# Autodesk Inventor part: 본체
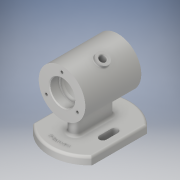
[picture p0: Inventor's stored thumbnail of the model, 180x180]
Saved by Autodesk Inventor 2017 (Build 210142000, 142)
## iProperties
Part Number: 본체
Material: 알루미늄 6061
Document SubType Name: Modeling
Designer: 601-13
Density: 2.7 g/cm^3
Appearance: 알루미늄 - 평지
Mass: 603.033 g
Surface Area: 453.222 cm^2
Volume: 223.346 cm^3
Author: 601-13
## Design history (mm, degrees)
sketch "스케치1"
  geometry: L1 (35.496, -38)-(-35.496, -38); L2 (35.496, 38)-(-35.496, 38); A1 r 52 centre (0, 0) between (-35.496, 38) and (-35.496, -38); A2 r 52 centre (0, 0) between (35.496, -38) and (35.496, 38); 3 further points
  constraints: 4 end point, 4 point on circle, 2 centre point, 2 horizontal, 2 midpoint, 2 vertical alignment, 1 coincident
  dimensions: "d2" = 76 distance between parallel lines of L2 L1; "d3" = 38 distance from line of L2 point (0, 0)
extrude "돌출1" new body sketch "스케치1" stored distance "d4" = 10; taper "d5" = 0 deg
sketch "스케치2"
  geometry: L1 (-19, 0)-(19, 0); L2 (-19, -7)-(19, -7); L3 (19, 7)-(-19, 7); L4 (-7.5, 24)-(7.5, 24); L5 (-7.5, 19.5)-(7.5, 19.5); L6 (7.5, 28.5)-(-7.5, 28.5); L7 (7.5, -28.5)-(-7.5, -28.5); L8 (-7.5, -19.5)-(7.5, -19.5); A1 r 7 centre (-19, 0) between (-19, 7) and (-19, -7); A2 r 7 centre (19, 0) between (19, -7) and (19, 7); A3 r 4.5 centre (-7.5, 24) between (-7.5, 28.5) and (-7.5, 19.5); A4 r 4.5 centre (7.5, 24) between (7.5, 19.5) and (7.5, 28.5); A5 r 4.5 centre (-7.5, -24) between (-7.5, -19.5) and (-7.5, -28.5); A6 r 4.5 centre (7.5, -24) between (7.5, -28.5) and (7.5, -19.5); 3 further points
  constraints: 20 end point, 12 point on circle, 8 tangent, 6 centre point, 6 symmetric about line, 2 horizontal, 2 midpoint, 2 parallel, 1 coincident, 1 vertical alignment, 2 other
  dimensions: "d6" = 14 diameter of A2; "d7" = 38 distance of L1.end L1.start; "d8" = 14 distance between parallel lines of L2 L3 (derived); "d9" = 9 diameter of A4; "d10" = 24 distance of point (0, 0) point (0, 24); "d11" = 15 distance of L4.end L4.start
node "작업 평면3"
sketch "스케치8"
  geometry: C1 r 42.5 at (0, 0); 1 further point
  constraints: 1 centre point, 1 coincident, 1 other
  dimensions: "d67" = 85 diameter of C1
feature "엠보싱2" sketch "스케치8" dims "d2" = 76, "d3" = 38, "d68" = 0.5, "d69" = 0
extrude "돌출2" cut sketch "스케치2" stored distance "d12" = 10; taper "d13" = 0 deg
sketch "스케치3"
  geometry: L1 (-36, 57)-(-36, 73); L2 (-36, 73)-(-24, 73); L3 (-24, 73)-(-24, 71); L4 (-24, 71)-(-20, 71); L5 (-20, 71)-(-20, 74.4); L6 (-20, 74.4)-(20, 74.4); L7 (20, 74.4)-(20, 71); L8 (20, 71)-(24, 71); L9 (24, 71)-(24, 73); L10 (24, 73)-(36, 73); L11 (36, 73)-(36, 57); L12 (36, 57)-(-36, 57); L13 (-36, 57)-(-36, 87); L14 (-36, 87)-(36, 87); L15 (36, 87)-(36, 57); L16 (35.496, -5)-(-35.496, -5) reference; 3 further points
  constraints: 30 end point, 11 perpendicular, 4 point on line, 2 midpoint, 2 vertical, 2 vertical alignment
  dimensions: "d14" = 16 distance of L1.start L1.end; "d15" = 14 distance between parallel lines of L12 L4; "d16" = 12 distance of L1.end L2.end; "d17" = 48 distance between parallel lines of L9 L3; "d18" = 40 distance between parallel lines of L7 L5; "d19" = 4 distance of L3.end L4.end; "d20" = 4 distance of L7.end L8.end (derived); "d21" = 12 distance of L9.end L10.end (derived); "d22" = 72 distance of L13.end L14.end (derived); "d23" = 30 distance of L1.start L13.end; "d31" = 62 distance from line of L16 point (0, 57)
revolve "회전1" stored, may be unused: angle "d25" = 90 deg
revolve "회전2" stored, may be unused: angle "d26" = 90 deg
extrude "돌출3" join sketch "스케치2" stored distance "d27" = 29; taper "d28" = 0 deg
sketch "스케치4" dims "d33" = 46
  geometry: L1 (-38, -62)-(38, -62) reference; 3 further points
  constraints: 2 vertical alignment, 2 other
  dimensions: "d32" = 62 distance from line of L1 point (0, 0)
hole "구멍1" sketch "스케치4" at (0, 23) diameter "d34" = 3.242; stored, may be unused: countersink angle "d38" = 90 deg, drill point angle "d40" = 118 deg; dims "d35" = 8, "d36" = 4, "d37" = 2, "d39" = 10
sketch "스케치5"
  geometry: L1 (57, 0)-(102.762, 0); L2 (57, 0)-(85.579, -16.5); C1 r 14 at (57, 0) reference; 1 further point
  constraints: 4 end point, 1 horizontal
  dimensions: "d44" = 30 deg angle of L1 L2; "d45" = 33 distance of L1.start L2.end
node "작업 평면1"
sketch "스케치6"
  geometry: C1 r 8 at (0, 0); C2 r 4 at (0, 0); 1 further point
  constraints: 2 centre point, 1 coincident
  dimensions: "d46" = 16 diameter of C1; "d47" = 8 diameter of C2
extrude "돌출4" join sketch "스케치6" stored distance "d48" = 29; taper "d49" = 0 deg
extrude "돌출5" cut sketch "스케치6" stored distance "d50" = 29; taper "d51" = 0 deg
fillet "모깎기1" dims "d52" = 1
fillet "모깎기2" dims "d53" = 1
fillet "모깎기3" dims "d57" = 0.3
fillet "모깎기4" dims "d58" = 0.3
fillet "모깎기5" dims "d59" = 3
fillet "모깎기6" dims "d60" = 3
chamfer "모따기1" distance "d61" = 1; stored, may be unused: second distance "d62" = 2, angle "d63" = 45 deg
fillet "모깎기7" dims "d64" = 3
node "솔리드1"
pattern_circular "원형 패턴1" dims angle "d42" = 360 deg
mirror "미러1"
other parameters: "d0" = 104, "d66" = 36
